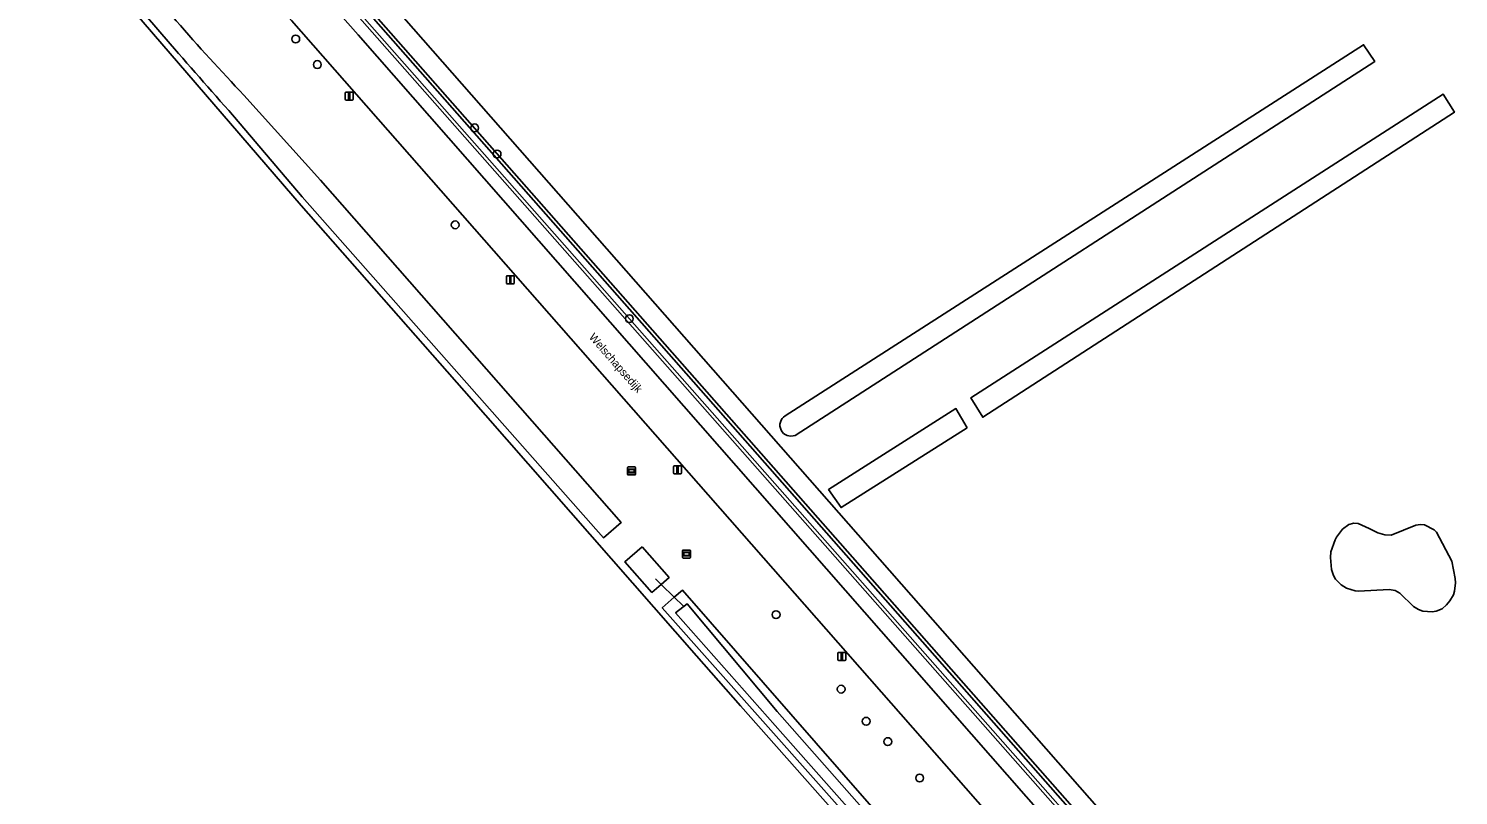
# Model space of a CAD drawing. Extents: x 156061 to 157804, y 383437 to 385640.
# Drawn here: x 157310.1 to 157488.8, y 384085.5 to 384181.3 of the extents above; entities that cross this region are included whole.
import ezdxf

# ---------------------------------------------------------------- set-up
doc = ezdxf.new("R2010")
doc.units = 0
for name, color, linetype in [('IMGEO_Berm_groen', 7, 'Continuous'), ('IMGEO_Boom', 7, 'Continuous'), ('IMGEO_Duiker', 7, 'Continuous'), ('IMGEO_Groenvoorziening', 7, 'Continuous'), ('IMGEO_Hek', 7, 'Continuous'), ('IMGEO_Lichtmast', 7, 'Continuous'), ('IMGEO_Oever', 7, 'Continuous'), ('IMGEO_Openbare_ruimte_label', 7, 'Continuous'), ('IMGEO_Rijbaan_lokaal_gesloten', 7, 'Continuous'), ('IMGEO_Terreindeel_zand', 7, 'Continuous'), ('IMGEO_Verklikker', 7, 'Continuous'), ('IMGEO_Waterloop', 7, 'Continuous')]:
    doc.layers.add(name, color=color, linetype=linetype)

msp = doc.modelspace()

# ---------------------------------------------------------------- linework, layer by layer
at = {"layer": 'IMGEO_Berm_groen'}
for points in [[(157340.41, 384192.86), (157351.29, 384180.48), (157461.84, 384054.56), (157463.91, 384056.38), (157463.38, 384056.98), (157462.83, 384056.5), (157343.68, 384191.47)], [(157318.6, 384190.2), (157317.96, 384189.64), (157344.19, 384159.18), (157364.55, 384136), (157393.61, 384102.92), (157399.11, 384096.66), (157446.05, 384043.69), (157456.41, 384032.18), (157483.79, 384000), (157500, 383980.87), (157519.27, 383957.9), (157520.38, 383958.3), (157500, 383982.12), (157484.69, 384000), (157449.42, 384041.22), (157450.46, 384042.19), (157447.97, 384045.05), (157446.91, 384044.08), (157389.32, 384108.91), (157390.82, 384110.23), (157391.84, 384111.13), (157448.89, 384045.9), (157456.76, 384052.82), (157342.96, 384182.28)], [(157337.04, 384172.94), (157346.6, 384162.34), (157384.17, 384119.56), (157381.99, 384117.67), (157344.33, 384160.24), (157335.13, 384171.03)]]:
    msp.add_lwpolyline(points, dxfattribs=at)
msp.add_lwpolyline([(157386.81, 384116.55), (157390.17, 384112.72), (157389.17, 384111.85), (157388.02, 384110.85), (157384.64, 384114.67)], close=True, dxfattribs=at)
for centre, radius, start, end in [((157599.37, 384420.91), 360.98, 219.399, 223.387), ((157895.42, 384671.13), 751.01, 219.81993, 221.75138)]:
    msp.add_arc(centre, radius, start, end, dxfattribs=at)
at = {"layer": 'IMGEO_Boom'}
for centre in [(157343.51, 384179.96), (157346.21, 384176.77), (157365.87, 384168.86), (157368.67, 384165.6), (157363.44, 384156.75), (157385.2, 384145.03), (157403.54, 384108.07), (157411.67, 384098.76), (157414.8, 384094.75), (157417.5, 384092.21), (157421.48, 384087.66)]:
    msp.add_circle(centre, 0.489, dxfattribs=at)
at = {"layer": 'IMGEO_Duiker'}
msp.add_lwpolyline([(157391.93, 384109.15), (157390.82, 384110.23), (157389.17, 384111.85), (157388.46, 384112.54)], dxfattribs=at)
at = {"layer": 'IMGEO_Groenvoorziening'}
for points in [[(157375.38, 384222.59), (157376.59, 384220.76), (157342.51, 384199.14), (157412.58, 384119.43), (157466.22, 384058.41), (157468.2, 384056.16), (157486.53, 384035.35), (157490.12, 384031.28), (157495.9, 384024.71), (157497.66, 384025.67), (157500, 384027.19), (157642, 384119.41), (157643.26, 384117.4), (157752.8, 384188.65), (157752.54, 384194.33), (157751.65, 384205.4), (157750.08, 384220.37), (157749.32, 384226.2), (157748.06, 384232.65), (157745.14, 384247.49), (157743.64, 384254.59), (157738.42, 384274.55), (157728.47, 384313.42)], [(157446.05, 384043.69), (157399.11, 384096.66), (157393.61, 384102.92), (157364.55, 384136), (157344.19, 384159.18), (157317.96, 384189.64), (157314.94, 384193.15), (157310.23, 384198.96), (157294.3, 384218.6), (157267.06, 384250), (157235.49, 384286.21)], [(157340.2, 384197.97), (157344.9, 384192.66), (157463.98, 384057.5), (157463.38, 384056.98), (157463.91, 384056.38), (157466.22, 384058.41), (157412.58, 384119.43), (157342.51, 384199.14), (157376.59, 384220.76), (157375.38, 384222.59), (157343.39, 384202.41)], [(157404.68, 384132.9), (157476.96, 384179.24)], [(157476.96, 384179.24), (157478.36, 384177.16), (157405.91, 384130.45)]]:
    msp.add_lwpolyline(points, dxfattribs=at)
for points in [[(157486.9, 384173.09), (157488.31, 384170.82), (157429.36, 384132.73), (157427.87, 384135.13)], [(157427.42, 384131.42), (157411.67, 384121.44), (157410.1, 384123.68), (157426.01, 384133.81)], [(157477.67, 384118.84), (157478.74, 384118.28), (157479.61, 384118.03), (157480.43, 384117.98), (157483.48, 384119.23), (157484.08, 384119.32), (157484.59, 384119.3), (157485.78, 384118.66), (157486.06, 384118.35), (157487.98, 384114.75), (157488.42, 384112.58), (157488.45, 384112.03), (157488.33, 384110.99), (157488.18, 384110.55), (157487.75, 384109.78), (157487.34, 384109.28), (157486.77, 384108.81), (157486.05, 384108.5), (157485.52, 384108.4), (157484.36, 384108.49), (157483.82, 384108.7), (157483.18, 384109.1), (157481.5, 384110.76), (157480.93, 384111.09), (157480.14, 384111.22), (157476.32, 384111.02), (157475.92, 384111.06), (157474.82, 384111.39), (157474.15, 384111.79), (157473.46, 384112.48), (157473.19, 384112.96), (157472.94, 384113.69), (157472.81, 384115.22), (157472.89, 384115.91), (157473.4, 384117.41), (157473.59, 384117.76), (157474.32, 384118.74), (157475.1, 384119.31), (157475.75, 384119.5), (157476.27, 384119.45)]]:
    msp.add_lwpolyline(points, close=True, dxfattribs=at)
msp.add_arc((157405.39, 384131.73), 1.37, 121.4925, 292.1619, dxfattribs=at)
at = {"layer": 'IMGEO_Hek'}
msp.add_lwpolyline([(157376.59, 384220.76), (157342.51, 384199.14), (157412.58, 384119.43), (157466.22, 384058.41)], dxfattribs=at)
at = {"layer": 'IMGEO_Lichtmast'}
for p, q in [((157349.68, 384172.44), (157349.68, 384173.23)), ((157349.68, 384173.23), (157349.68, 384172.44)), ((157349.78, 384173.33), (157350.57, 384173.33)), ((157350.57, 384173.33), (157349.78, 384173.33)), ((157350.67, 384173.23), (157350.67, 384172.44)), ((157350.67, 384172.44), (157350.67, 384173.23)), ((157350.57, 384172.34), (157349.78, 384172.34)), ((157349.78, 384172.34), (157350.57, 384172.34)), ((157369.83, 384149.5), (157369.83, 384150.29)), ((157369.83, 384150.29), (157369.83, 384149.5)), ((157369.93, 384150.39), (157370.72, 384150.39)), ((157370.72, 384150.39), (157369.93, 384150.39)), ((157370.72, 384149.4), (157369.93, 384149.4)), ((157369.93, 384149.4), (157370.72, 384149.4)), ((157370.82, 384150.29), (157370.82, 384149.5)), ((157370.82, 384149.5), (157370.82, 384150.29)), ((157390.73, 384125.76), (157390.73, 384126.56)), ((157390.73, 384126.56), (157390.73, 384125.76)), ((157390.83, 384126.66), (157391.61, 384126.66)), ((157391.61, 384126.66), (157390.83, 384126.66)), ((157391.71, 384126.56), (157391.71, 384125.76)), ((157391.71, 384125.76), (157391.71, 384126.56)), ((157391.61, 384125.66), (157390.83, 384125.66)), ((157390.83, 384125.66), (157391.61, 384125.66)), ((157411.27, 384102.45), (157411.27, 384103.25)), ((157411.27, 384103.25), (157411.27, 384102.45)), ((157411.37, 384103.35), (157412.16, 384103.35)), ((157412.16, 384103.35), (157411.37, 384103.35)), ((157412.26, 384103.25), (157412.26, 384102.45)), ((157412.26, 384102.45), (157412.26, 384103.25)), ((157412.16, 384102.35), (157411.37, 384102.35)), ((157411.37, 384102.35), (157412.16, 384102.35))]:
    msp.add_line(p, q, dxfattribs=at)
for points in [[(157350.1, 384173.21), (157350.25, 384173.21), (157350.25, 384172.46), (157350.1, 384172.46), (157350.1, 384173.21)], [(157370.25, 384150.27), (157370.4, 384150.27), (157370.4, 384149.52), (157370.25, 384149.52), (157370.25, 384150.27)], [(157391.14, 384126.54), (157391.3, 384126.54), (157391.3, 384125.79), (157391.14, 384125.79), (157391.14, 384126.54)], [(157411.69, 384103.23), (157411.84, 384103.23), (157411.84, 384102.48), (157411.69, 384102.48), (157411.69, 384103.23)]]:
    msp.add_lwpolyline(points, dxfattribs=at)
for centre, start, end in [((157349.78, 384173.23), 90, 180), ((157349.78, 384173.23), 90, 180), ((157349.78, 384172.44), 180, 270), ((157349.78, 384172.44), 180, 270), ((157350.57, 384173.23), 0, 90), ((157350.57, 384173.23), 360, 90), ((157350.57, 384172.44), 270, 0), ((157350.57, 384172.44), 270, 0), ((157369.93, 384150.29), 90, 180), ((157369.93, 384150.29), 90, 180), ((157369.93, 384149.5), 180, 270), ((157369.93, 384149.5), 180, 270), ((157370.72, 384150.29), 0, 90), ((157370.72, 384150.29), 360, 90), ((157370.72, 384149.5), 270, 0), ((157370.72, 384149.5), 270, 0), ((157390.83, 384126.56), 90, 180), ((157390.83, 384126.56), 90, 180), ((157391.61, 384126.56), 0, 90), ((157391.61, 384126.56), 360, 90), ((157390.83, 384125.76), 180, 270), ((157390.83, 384125.76), 180, 270), ((157391.61, 384125.76), 270, 0), ((157391.61, 384125.76), 270, 0), ((157411.37, 384103.25), 90, 180), ((157411.37, 384103.25), 90, 180), ((157412.16, 384103.25), 0, 90), ((157412.16, 384103.25), 360, 90), ((157411.37, 384102.45), 180, 270), ((157411.37, 384102.45), 180, 270), ((157412.16, 384102.45), 270, 0), ((157412.16, 384102.45), 270, 0)]:
    msp.add_arc(centre, 0.1, start, end, dxfattribs=at)
at = {"layer": 'IMGEO_Oever'}
for points in [[(157343.68, 384191.47), (157462.83, 384056.5), (157463.38, 384056.98), (157463.98, 384057.5), (157344.9, 384192.66)], [(157344.59, 384192.37), (157463.38, 384057.54), (157463.1, 384057.3), (157462.87, 384057.1), (157385.2, 384145.03), (157343.99, 384191.76)]]:
    msp.add_lwpolyline(points, dxfattribs=at)
for points in [[(157391.84, 384111.13), (157390.82, 384110.23), (157389.32, 384108.91), (157446.91, 384044.08), (157447.97, 384045.05), (157448.89, 384045.9)], [(157446.42, 384045.66), (157404.4, 384093.13), (157390.98, 384108.29), (157392.43, 384109.4), (157403.68, 384095.98), (157443.49, 384050.82), (157447.27, 384046.27)]]:
    msp.add_lwpolyline(points, close=True, dxfattribs=at)
at = {"layer": 'IMGEO_Rijbaan_lokaal_gesloten'}
msp.add_lwpolyline([(157461.84, 384054.56), (157351.29, 384180.48), (157340.41, 384192.86), (157332.28, 384202.11), (157328.46, 384198.78), (157342.96, 384182.28), (157456.76, 384052.82)], dxfattribs=at)
at = {"layer": 'IMGEO_Terreindeel_zand'}
msp.add_lwpolyline([(157477.67, 384118.84), (157476.27, 384119.45), (157475.75, 384119.5), (157475.1, 384119.31), (157474.32, 384118.74), (157473.59, 384117.76), (157473.4, 384117.41), (157472.89, 384115.91), (157472.81, 384115.22), (157472.94, 384113.69), (157473.19, 384112.96), (157473.46, 384112.48), (157474.15, 384111.79), (157474.82, 384111.39), (157475.92, 384111.06), (157476.32, 384111.02), (157480.14, 384111.22), (157480.93, 384111.09), (157481.5, 384110.76), (157483.18, 384109.1), (157483.82, 384108.7), (157484.36, 384108.49), (157485.52, 384108.4), (157486.05, 384108.5), (157486.77, 384108.81), (157487.34, 384109.28), (157487.75, 384109.78), (157488.18, 384110.55), (157488.33, 384110.99), (157488.45, 384112.03), (157488.42, 384112.58), (157487.98, 384114.75), (157486.06, 384118.35), (157485.78, 384118.66), (157484.59, 384119.3), (157484.08, 384119.32), (157483.48, 384119.23), (157480.43, 384117.98), (157479.61, 384118.03), (157478.74, 384118.28)], close=True, dxfattribs=at)
at = {"layer": 'IMGEO_Verklikker'}
for p, q in [((157384.97, 384125.61), (157384.97, 384126.41)), ((157384.97, 384126.41), (157384.97, 384125.61)), ((157385.07, 384126.51), (157385.86, 384126.51)), ((157385.86, 384126.51), (157385.07, 384126.51)), ((157385.96, 384126.41), (157385.96, 384125.61)), ((157385.96, 384125.61), (157385.96, 384126.41)), ((157385.86, 384125.51), (157385.07, 384125.51)), ((157385.07, 384125.51), (157385.86, 384125.51)), ((157391.84, 384115.24), (157391.84, 384116.04)), ((157391.84, 384116.04), (157391.84, 384115.24)), ((157391.94, 384116.14), (157392.73, 384116.14)), ((157392.73, 384116.14), (157391.94, 384116.14)), ((157392.83, 384116.04), (157392.83, 384115.24)), ((157392.83, 384115.24), (157392.83, 384116.04)), ((157392.73, 384115.14), (157391.94, 384115.14)), ((157391.94, 384115.14), (157392.73, 384115.14))]:
    msp.add_line(p, q, dxfattribs=at)
for points in [[(157385.07, 384126.25), (157385.86, 384126.25), (157385.86, 384125.78), (157385.07, 384125.78), (157385.07, 384126.25)], [(157385.14, 384126.18), (157385.14, 384125.85), (157385.79, 384125.85), (157385.79, 384126.18), (157385.14, 384126.18)], [(157391.94, 384115.87), (157392.73, 384115.87), (157392.73, 384115.41), (157391.94, 384115.41), (157391.94, 384115.87)], [(157392, 384115.81), (157392, 384115.47), (157392.66, 384115.47), (157392.66, 384115.81), (157392, 384115.81)]]:
    msp.add_lwpolyline(points, dxfattribs=at)
for centre, start, end in [((157385.07, 384126.41), 90, 180), ((157385.07, 384126.41), 90, 180), ((157385.86, 384126.41), 0, 90), ((157385.86, 384126.41), 360, 90), ((157385.07, 384125.61), 180, 270), ((157385.07, 384125.61), 180, 270), ((157385.86, 384125.61), 270, 0), ((157385.86, 384125.61), 270, 0), ((157391.94, 384116.04), 90, 180), ((157391.94, 384116.04), 90, 180), ((157391.94, 384115.24), 180, 270), ((157391.94, 384115.24), 180, 270), ((157392.73, 384116.04), 0, 90), ((157392.73, 384116.04), 360, 90), ((157392.73, 384115.24), 270, 0), ((157392.73, 384115.24), 270, 0)]:
    msp.add_arc(centre, 0.1, start, end, dxfattribs=at)
at = {"layer": 'IMGEO_Waterloop'}
for points in [[(157343.99, 384191.76), (157385.2, 384145.03), (157462.87, 384057.1), (157463.1, 384057.3), (157463.38, 384057.54), (157344.59, 384192.37)], [(157405.91, 384130.45), (157478.36, 384177.16), (157476.96, 384179.24), (157404.68, 384132.9)], [(157335.13, 384171.03), (157344.33, 384160.24), (157381.99, 384117.67), (157384.17, 384119.56), (157346.6, 384162.34), (157337.04, 384172.94)]]:
    msp.add_lwpolyline(points, dxfattribs=at)
for points in [[(157488.31, 384170.82), (157486.9, 384173.09), (157427.87, 384135.13), (157429.36, 384132.73)], [(157427.42, 384131.42), (157426.01, 384133.81), (157410.1, 384123.68), (157411.67, 384121.44)], [(157386.81, 384116.55), (157384.64, 384114.67), (157388.02, 384110.85), (157389.17, 384111.85), (157390.17, 384112.72)], [(157446.42, 384045.66), (157447.27, 384046.27), (157443.49, 384050.82), (157403.68, 384095.98), (157392.43, 384109.4), (157390.98, 384108.29), (157404.4, 384093.13)]]:
    msp.add_lwpolyline(points, close=True, dxfattribs=at)
for centre, radius, start, end in [((157599.37, 384420.91), 360.98, 219.399, 223.387), ((157895.42, 384671.13), 751.01, 219.81993, 221.75138), ((157405.39, 384131.73), 1.37, 121.4925, 292.1619)]:
    msp.add_arc(centre, radius, start, end, dxfattribs=at)

# ---------------------------------------------------------------- texts
at = {"layer": 'IMGEO_Openbare_ruimte_label'}
msp.add_text('Welschapsedijk', height=1, rotation=311.0674, dxfattribs=at).set_placement((157380.09, 384142.68))

doc.saveas('drawing.dxf')
